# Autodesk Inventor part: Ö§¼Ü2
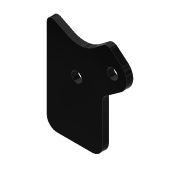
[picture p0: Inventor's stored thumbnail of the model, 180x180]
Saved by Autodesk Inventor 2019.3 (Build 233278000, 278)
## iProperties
Created: 2017-10
Part Number: Ö§¼Ü2
Material: Ogólny
Document SubType Name: Modeling
Designer: CADENGINEERING4
Density: 1 g/cm^3
Appearance: Gładki — czarny
Author: CADENGINEERING4
Revision Number: ÈÎºÎ
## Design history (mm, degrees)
feature "ÇÐ³ý-À­Éì1"
node "Bryła1"
